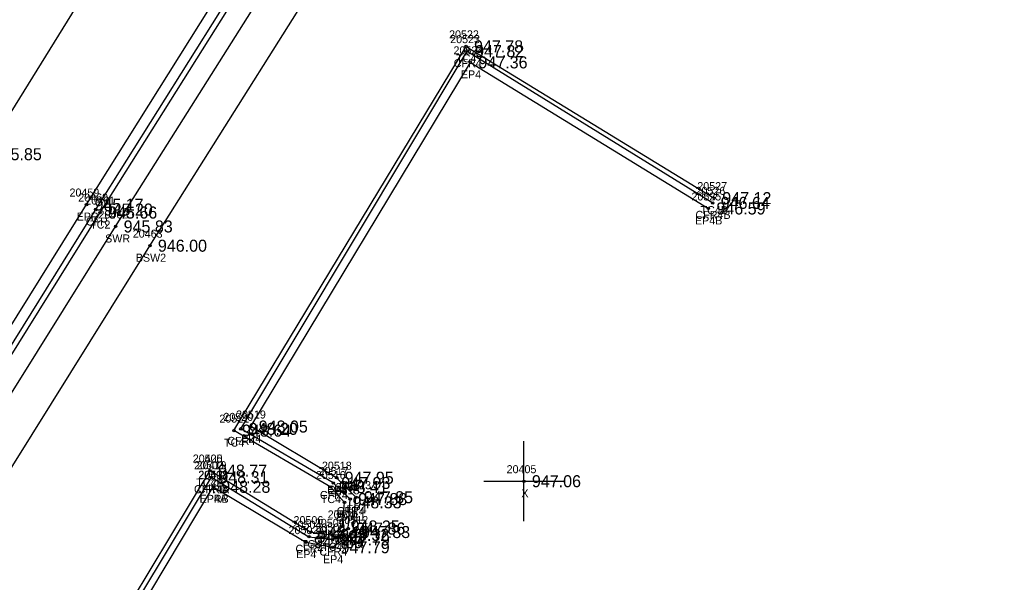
# Model space of a CAD drawing. Extents: x 1576181 to 1577685, y 1099396 to 1101490.
# Drawn here: x 1576527.1 to 1576651.4, y 1099717.4 to 1099787.6 of the extents above; entities that cross this region are included whole.
import ezdxf

# ---------------------------------------------------------------- set-up
doc = ezdxf.new("R2010")
doc.units = 0
for name, color, linetype in [('RD_DTM_BkLn1', 7, 'Continuous'), ('RD_DTM_BkLn2', 7, 'Continuous'), ('RD_EX_Conc', 7, 'Continuous'), ('RD_EX_Conc_txCode', 7, 'Continuous'), ('RD_EX_Misc', 7, 'Continuous'), ('RD_EX_Misc_txCode', 7, 'Continuous'), ('RD_EX_Road', 7, 'Continuous'), ('RD_EX_Road_txCode', 7, 'Continuous'), ('RD_EX_TX_Conc_ELEV', 7, 'Continuous'), ('RD_EX_TX_Misc_ELEV', 7, 'Continuous'), ('RD_EX_TX_Road_ELEV', 7, 'Continuous'), ('RD_HC_Survey_ELEV', 7, 'Continuous'), ('RD_SMD_Locator', 7, 'Continuous')]:
    doc.layers.add(name, color=color, linetype=linetype)

msp = doc.modelspace()

# ---------------------------------------------------------------- linework, layer by layer
at = {"layer": 'RD_DTM_BkLn1'}
msp.add_lwpolyline([(1576435.96, 1099635.47), (1576469.98, 1099685.91), (1576496.51, 1099728.46), (1576522.67, 1099770.85), (1576549.06, 1099813.4), (1576563.36, 1099837.2), (1576575.09, 1099855.95), (1576600.75, 1099898.96), (1576625.57, 1099942.14), (1576652.37, 1099988.91), (1576675.03, 1100029.12), (1576699.51, 1100072.44), (1576723.52, 1100115.7), (1576748.08, 1100158.53), (1576774.13, 1100203.85), (1576797.97, 1100246.52), (1576822.46, 1100289.82), (1576846.93, 1100333.35), (1576871.37, 1100376.46), (1576888.27, 1100406.22)], dxfattribs=at)
at = {"layer": 'RD_DTM_BkLn2'}
for points in [[(1576453.65, 1099622.74), (1576484.93, 1099677.43), (1576510.27, 1099720.56), (1576537.09, 1099763.56), (1576564.3, 1099806.82), (1576572.37, 1099816.55), (1576577.32, 1099819.84)], [(1576550.83, 1099731.33), (1576563.44, 1099723.64), (1576566.09, 1099723.3), (1576567.4, 1099724.35), (1576567.63, 1099727.36), (1576565.91, 1099729.27), (1576553.82, 1099736.32), (1576582.82, 1099784.32), (1576613.84, 1099765.36)], [(1576511.92, 1099607.05), (1576510.37, 1099614.53), (1576509.23, 1099617.04), (1576507.41, 1099618.75), (1576489.23, 1099629.49), (1576513, 1099668.8), (1576536.11, 1099706.87), (1576550.83, 1099731.33)]]:
    msp.add_lwpolyline(points, dxfattribs=at)
at = {"layer": 'RD_EX_Conc'}
for points in [[(1576450.24, 1099618.33), (1576484.56, 1099677.8), (1576510.13, 1099721.55), (1576536.54, 1099763.94), (1576563.69, 1099807.11), (1576571.96, 1099817.02), (1576576.78, 1099820.05)], [(1576453.65, 1099622.74), (1576455.84, 1099621.56), (1576487.04, 1099675.93), (1576513, 1099720.16), (1576539.03, 1099761.82), (1576566.5, 1099805.38), (1576570.9, 1099812.6)], [(1576460.33, 1099619.05), (1576491.05, 1099673.04), (1576516.28, 1099716.12), (1576543.31, 1099759.42), (1576570.5, 1099802.59), (1576575.6, 1099809.12)], [(1576550.99, 1099730.5), (1576563.18, 1099723.06), (1576566.16, 1099722.72), (1576568.09, 1099724.09), (1576568.34, 1099727.77), (1576566.23, 1099729.78), (1576554.66, 1099736.54), (1576582.96, 1099783.72), (1576613.64, 1099764.77)], [(1576512.55, 1099607.18), (1576510.94, 1099614.7), (1576509.78, 1099617.42), (1576507.67, 1099619.31), (1576489.95, 1099629.7), (1576513.43, 1099668.52), (1576536.7, 1099706.66), (1576550.99, 1099730.5)]]:
    msp.add_lwpolyline(points, dxfattribs=at)
at = {"layer": 'RD_EX_Misc'}
for p, q in [((1576590.05, 1099725), (1576590.05, 1099735)), ((1576585.05, 1099730), (1576595.05, 1099730))]:
    msp.add_line(p, q, dxfattribs=at)
at = {"layer": 'RD_EX_Road'}
for points in [[(1576450.24, 1099618.33), (1576449.12, 1099618.92), (1576483.24, 1099678.31), (1576508.19, 1099720.98), (1576535.39, 1099764.56), (1576562.56, 1099807.86), (1576568.65, 1099815.29), (1576571.43, 1099817.5), (1576576.56, 1099821.02), (1576582.03, 1099822.66), (1576588.16, 1099823.79), (1576596.81, 1099822.84), (1576604.56, 1099819.9), (1576624.36, 1099808.15), (1576638.14, 1099802.71)], [(1576551.23, 1099729.3), (1576562.8, 1099722.39), (1576566.14, 1099721.75), (1576568.7, 1099723.65), (1576569.06, 1099728), (1576566.65, 1099730.44), (1576555.91, 1099736.83), (1576583.37, 1099782.32), (1576613.11, 1099764.07)], [(1576513.37, 1099607.48), (1576511.79, 1099614.93), (1576510.39, 1099617.93), (1576508.02, 1099620.01), (1576491.05, 1099629.97), (1576514.12, 1099668.03), (1576537.42, 1099706.25), (1576551.23, 1099729.3)]]:
    msp.add_lwpolyline(points, dxfattribs=at)
at = {"layer": 'RD_SMD_Locator'}
for centre in [(1576582.82, 1099784.32), (1576582.96, 1099783.72), (1576583.37, 1099782.32), (1576613.84, 1099765.36), (1576535.39, 1099764.56), (1576536.54, 1099763.94), (1576537.09, 1099763.56), (1576613.11, 1099764.07), (1576613.64, 1099764.77), (1576539.03, 1099761.82), (1576543.31, 1099759.42), (1576553.82, 1099736.32), (1576554.66, 1099736.54), (1576555.91, 1099736.83), (1576550.83, 1099731.33), (1576550.83, 1099731.33), (1576550.99, 1099730.5), (1576550.99, 1099730.5), (1576566.65, 1099730.44), (1576590.05, 1099730), (1576551.23, 1099729.3), (1576551.23, 1099729.3), (1576565.91, 1099729.27), (1576566.23, 1099729.78), (1576568.34, 1099727.77), (1576569.06, 1099728), (1576567.63, 1099727.36), (1576567.4, 1099724.35), (1576568.09, 1099724.09), (1576563.18, 1099723.06), (1576563.44, 1099723.64), (1576566.09, 1099723.3), (1576566.16, 1099722.72), (1576568.7, 1099723.65), (1576562.8, 1099722.39), (1576566.14, 1099721.75)]:
    msp.add_circle(centre, 0.15, dxfattribs=at)

# ---------------------------------------------------------------- texts
at = {"layer": 'RD_EX_Conc_txCode'}
for s, p in [('20522', (1576580.7, 1099785.32)), ('20523', (1576580.84, 1099784.72)), ('CFR4', (1576581.28, 1099781.72)), ('TC4', (1576581.58, 1099782.32)), ('20526', (1576611.5, 1099765.77)), ('20527', (1576611.72, 1099766.36)), ('20460', (1576534.36, 1099764.94)), ('20461', (1576535.24, 1099764.56)), ('20462', (1576536.89, 1099762.82)), ('CFR4B', (1576611.49, 1099762.77)), ('TC4B', (1576612.13, 1099763.36)), ('CFR', (1576535.31, 1099761.94)), ('TC2', (1576535.85, 1099761.56)), ('20463', (1576541.17, 1099760.42)), ('SWR', (1576537.72, 1099759.82)), ('BSW2', (1576541.55, 1099757.42)), ('20521', (1576551.99, 1099737.32)), ('20520', (1576552.5, 1099737.54)), ('TC4', (1576552.58, 1099734.32)), ('CFR4', (1576552.98, 1099734.54)), ('20420', (1576548.67, 1099732.33)), ('20505', (1576548.67, 1099732.33)), ('20503', (1576548.83, 1099731.5)), ('20419', (1576549.16, 1099731.5)), ('20517', (1576564.4, 1099730.78)), ('TC4A', (1576549.1, 1099729.33)), ('TC2B', (1576549.12, 1099729.33)), ('20516', (1576564.05, 1099730.27)), ('CFR4A', (1576548.82, 1099728.5)), ('CFRB', (1576549.29, 1099728.5)), ('20515', (1576565.79, 1099728.36)), ('20514', (1576566.51, 1099728.77)), ('CFR4', (1576564.56, 1099727.78)), ('TC4', (1576564.67, 1099727.27)), ('CFR4', (1576566.67, 1099725.77)), ('20506', (1576561.26, 1099724.64)), ('20509', (1576563.93, 1099724.3)), ('20510', (1576565.53, 1099725.35)), ('TC4', (1576566.38, 1099725.36)), ('20511', (1576566.54, 1099725.09)), ('20504', (1576561.03, 1099724.06)), ('20508', (1576564, 1099723.72)), ('TC4', (1576562.19, 1099721.64)), ('TC4', (1576566.16, 1099722.35)), ('CFR4', (1576566.41, 1099722.09)), ('CFR4', (1576561.51, 1099721.06)), ('CFR4', (1576564.48, 1099720.72)), ('TC4', (1576564.85, 1099721.3))]:
    msp.add_text(s, height=1, dxfattribs=at).set_placement(p)
at = {"layer": 'RD_EX_Misc_txCode'}
for s, p in [('20405', (1576587.89, 1099731)), ('X', (1576589.73, 1099728))]:
    msp.add_text(s, height=1, dxfattribs=at).set_placement(p)
at = {"layer": 'RD_EX_Road_txCode'}
for s, p in [('20524', (1576581.25, 1099783.32)), ('EP4', (1576582.17, 1099780.32)), ('20459', (1576533.27, 1099765.56)), ('20525', (1576610.99, 1099765.07)), ('EPR', (1576534.16, 1099762.56)), ('EP4B', (1576611.43, 1099762.07)), ('20519', (1576554.08, 1099737.83)), ('EP4', (1576554.71, 1099734.83)), ('20518', (1576564.81, 1099731.44)), ('20501', (1576549.35, 1099730.3)), ('20418', (1576549.39, 1099730.3)), ('EP4', (1576565.44, 1099728.44)), ('20513', (1576567.23, 1099729)), ('EPRB', (1576549.52, 1099727.3)), ('EP4A', (1576549.53, 1099727.3)), ('EP4', (1576567.86, 1099726)), ('20512', (1576566.87, 1099724.65)), ('20502', (1576560.64, 1099723.39)), ('20507', (1576563.99, 1099722.75)), ('EP4', (1576567.5, 1099721.65)), ('EP4', (1576561.59, 1099720.39)), ('EP4', (1576564.94, 1099719.75))]:
    msp.add_text(s, height=1, dxfattribs=at).set_placement(p)
at = {"layer": 'RD_EX_TX_Conc_ELEV'}
for s, p in [('947.78', (1576583.82, 1099783.57)), ('947.82', (1576583.96, 1099782.97)), ('946.64', (1576614.64, 1099764.02)), ('947.12', (1576614.84, 1099764.61)), ('945.20', (1576537.54, 1099763.19)), ('945.66', (1576538.09, 1099762.81)), ('945.83', (1576540.03, 1099761.07)), ('946.00', (1576544.31, 1099758.67)), ('948.64', (1576554.82, 1099735.57)), ('948.20', (1576555.66, 1099735.79)), ('948.77', (1576551.83, 1099730.58)), ('948.77', (1576551.83, 1099730.58)), ('948.31', (1576551.99, 1099729.75)), ('948.31', (1576551.99, 1099729.75)), ('947.93', (1576567.23, 1099729.03)), ('948.41', (1576566.91, 1099728.52)), ('948.33', (1576568.63, 1099726.61)), ('947.88', (1576569.34, 1099727.02)), ('948.40', (1576564.44, 1099722.89)), ('948.32', (1576567.09, 1099722.55)), ('948.35', (1576568.4, 1099723.6)), ('947.86', (1576569.09, 1099723.34)), ('947.92', (1576564.18, 1099722.31)), ('947.79', (1576567.16, 1099721.97))]:
    msp.add_text(s, height=1.5, dxfattribs=at).set_placement(p)
at = {"layer": 'RD_EX_TX_Misc_ELEV'}
msp.add_text('947.06', height=1.5, dxfattribs=at).set_placement((1576591.05, 1099729.25))
at = {"layer": 'RD_EX_TX_Road_ELEV'}
for s, p in [('947.36', (1576584.37, 1099781.57)), ('945.17', (1576536.39, 1099763.81)), ('946.59', (1576614.11, 1099763.32)), ('948.05', (1576556.91, 1099736.08)), ('947.95', (1576567.65, 1099729.69)), ('948.28', (1576552.23, 1099728.55)), ('948.28', (1576552.23, 1099728.55)), ('947.85', (1576570.06, 1099727.25)), ('947.83', (1576569.7, 1099722.9)), ('947.89', (1576563.8, 1099721.64)), ('947.79', (1576567.14, 1099721))]:
    msp.add_text(s, height=1.5, dxfattribs=at).set_placement(p)
at = {"layer": 'RD_HC_Survey_ELEV'}
msp.add_text('945.85', height=1.5, dxfattribs=at).set_placement((1576523.67, 1099770.1))

doc.saveas('drawing.dxf')
